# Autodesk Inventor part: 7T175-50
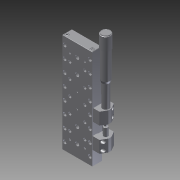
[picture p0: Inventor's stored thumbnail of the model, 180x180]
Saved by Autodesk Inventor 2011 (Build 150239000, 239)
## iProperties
Created: 2012-04
Part Number: 7T175-50
Document SubType Name: Modeling
Designer: vadybininkas6
Density: 1 g/cm^3
Author: vadybininkas6
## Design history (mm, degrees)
feature "Base1"
body "Solid1"
